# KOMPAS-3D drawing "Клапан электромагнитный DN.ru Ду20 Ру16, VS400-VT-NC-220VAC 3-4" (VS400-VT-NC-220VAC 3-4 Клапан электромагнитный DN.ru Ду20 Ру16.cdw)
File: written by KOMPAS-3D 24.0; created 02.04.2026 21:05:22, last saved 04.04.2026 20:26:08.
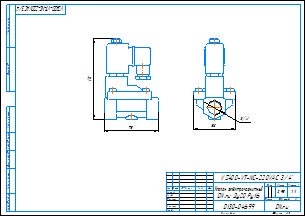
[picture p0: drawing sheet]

Document properties: c3d_UniqueCompID: ef56311e-7521-43dc-8291-0e6108b3d81d; Обозначение: VS400-ET-NC-220VAC 1-2; Наименование: Клапан электромагнитный DN.ru Ду15 Ру16; Автор: artio; Класс точности: c; Знак неуказанной шероховатости: Шероховатость не задана; Рассекать на разрезах: Да; c3d_UniqueCompID: ef56311e-7521-43dc-8291-0e6108b3d81d; Обозначение: VS400-ET-NC-220VAC 3-4; Наименование: Клапан электромагнитный DN.ru Ду20 Ру16; Автор: artio; Класс точности: c; Знак неуказанной шероховатости: Шероховатость не задана; Рассекать на разрезах: Да; c3d_UniqueCompID: ef56311e-7521-43dc-8291-0e6108b3d81d; Обозначение: VS400-ET-NC-220VAC 3-8; Наименование: Клапан электромагнитный DN.ru Ду10 Ру16; Автор: artio; Класс точности: c; Знак неуказанной шероховатости: Шероховатость не задана; Рассекать на разрезах: Да; Автор: artio; Форматы листов документа: A3; Полное имя файла: VS400-VT-NC-220VAC 3-4 Клапан электромагнитный DN.ru Ду20 Ру16.m3d; Масса: 0.954; Наименование: Клапан электромагнитный DN.ru Ду20 Ру16; Количество листов документа: 1; Примечание: D130-04699

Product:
- Body: Тело 1  | qty 1
    Масса: 1.210539
- Part/product: Клапан электромагнитный DN.ru Ду20 Ру16  | designation VS400-VT-NC-220VAC 3-4
    Масса: 0.954
    Раздел спецификации: Прочие изделия
    Примечание: D130-04699
    additional columns: ef56311e-7521-43dc-8291-0e6108b3d81d; VS400-ET-NC-220VAC 3-4; artio; c; Шероховатость не задана; Да

Views: Вид 1, Спереди, Проекционный вид 2
Referenced files in C:\Users\artio\OneDrive\Рабочий стол\Клапан электромагнитный DN.ru VS4x-xT-NC-x\DN10\: VS400-ET-NC-220VAC 3-8 Клапан электромагнитный DN.ru Ду10 Ру16.m3d, VS400-ET-NC-220VAC 3-8 Клапан электромагнитный DN.ru Ду10 Ру16.cdw
Referenced files in C:\Users\artio\OneDrive\Рабочий стол\Клапан электромагнитный DN.ru\VS400-VT-NC\VS400-VT-NC-220VAC\: VS400-VT-NC-220VAC 3-4 Клапан электромагнитный DN.ru Ду20 Ру16.m3d
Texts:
  VS400-VT-NC-220VAC 3-4
  Линейный размер
  Клапан электромагнитный
  DN.ru Ду20 Ру16
  VS400-VT-NC-220VAC 3/4"
  VS400-VT-NC-220VAC 3/4"-
  Клапан электромагнитный DN.ru Ду20 Ру16
  VS400-VT-NC-220VAC 3-4 Клапан электромагнитный DN.ru Ду20 Ру16
Dimensions and other numbers on the sheet: 0; 3; 2; 4; 58; 3/4"; 75; 112; 1:1; 1; 0,95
